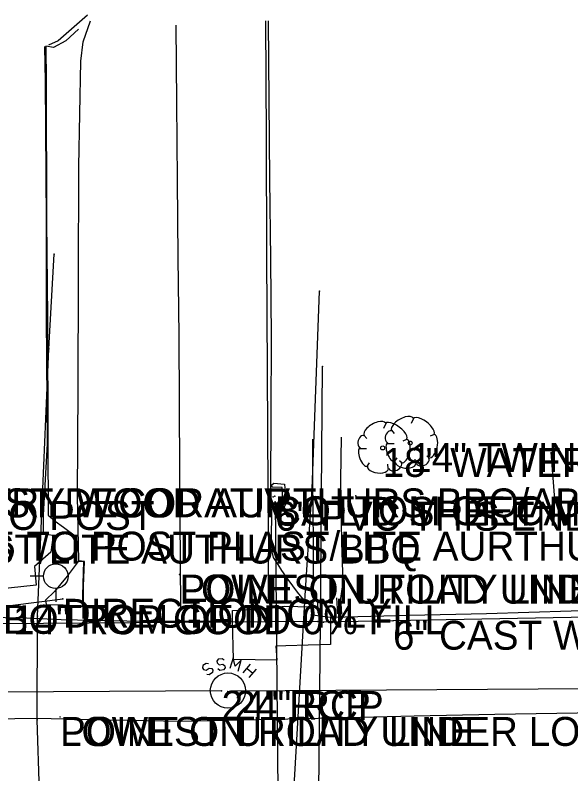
# Model space of a CAD drawing. Extents: x 1304270 to 1306561, y 1876019 to 1876752.
# Drawn here: x 1305896.1 to 1305992.1, y 1876400.4 to 1876531.4 of the extents above; entities that cross this region are included whole.
import ezdxf

# ---------------------------------------------------------------- set-up
doc = ezdxf.new("R2010")
doc.units = 0
for name, color, linetype in [('S_BUILDING_ANNOT', 7, 'Continuous'), ('S_CROSS_DRAIN', 7, 'Continuous'), ('S_CROSS_DRAIN_ANNOT', 7, 'Continuous'), ('S_CURB', 7, 'Continuous'), ('S_DRG_PT_SYM', 7, 'Continuous'), ('S_EDGE_CONCRETE', 7, 'Continuous'), ('S_EDGE_PAVEMENT', 7, 'Continuous'), ('S_ELECTRIC_UTILITIES_ANNOT', 7, 'Continuous'), ('S_FENCE_ANNOT', 7, 'Continuous'), ('S_FIBER_OPTIC_CABLE', 7, 'Continuous'), ('S_GAS_UTILITIES', 7, 'Continuous'), ('S_MANHOLE_ANNOT', 7, 'Continuous'), ('S_MSC_PT_SYM', 7, 'Continuous'), ('S_PARKING', 7, 'Continuous'), ('S_PAVEMENT_CROWN', 7, 'Continuous'), ('S_SANITARY_SEWER', 7, 'Continuous'), ('S_SANITARY_SEWER_ANNOT', 7, 'Continuous'), ('S_SIDEWALK', 7, 'Continuous'), ('S_SIGN_ANNOT', 7, 'Continuous'), ('S_STORM_SEWER', 7, 'Continuous'), ('S_STORM_SEWER_ANNOT', 7, 'Continuous'), ('S_SURVEY_TEXT_ANNOT', 7, 'Continuous'), ('S_TREE', 7, 'Continuous'), ('S_TREE_ANNOT', 7, 'Continuous'), ('S_UTILITY_POLE', 7, 'Continuous'), ('S_UTL_PT_SYM', 7, 'Continuous'), ('S_WATER_UTILITIES', 7, 'Continuous'), ('S_WATER_UTILITIES_ANNOT', 7, 'Continuous')]:
    doc.layers.add(name, color=color, linetype=linetype)

msp = doc.modelspace()

# ---------------------------------------------------------------- linework, layer by layer
at = {"layer": 'S_CROSS_DRAIN'}
msp.add_line((1305895.71, 1876429.5), (1305904.32, 1876430.63), dxfattribs=at)
at = {"layer": 'S_CURB'}
for points in [[(1305908.59, 1876531.43), (1305903.51, 1876527.02), (1305901.83, 1876526.26)], [(1305940.28, 1876449.7), (1305940.32, 1876462.66), (1305940.37, 1876475.63), (1305940.25, 1876489.33), (1305940.12, 1876503.04), (1305940, 1876516.74), (1305939.88, 1876530.45)], [(1305940.41, 1876440.32), (1305940.45, 1876446.22)]]:
    msp.add_lwpolyline(points, dxfattribs=at)
at = {"layer": 'S_DRG_PT_SYM'}
for points in [[(1305939.98, 1876448.32), (1305939.98, 1876448.37), (1305939.98, 1876448.32), (1305939.93, 1876448.32), (1305939.98, 1876448.32), (1305939.98, 1876448.27), (1305939.98, 1876448.32), (1305940.03, 1876448.32)], [(1305904.32, 1876430.63), (1305904.32, 1876430.68), (1305904.32, 1876430.63), (1305904.27, 1876430.63), (1305904.32, 1876430.63), (1305904.32, 1876430.58), (1305904.32, 1876430.63), (1305904.37, 1876430.63)]]:
    msp.add_lwpolyline(points, dxfattribs=at)
at = {"layer": 'S_EDGE_CONCRETE'}
for points in [[(1305907.04, 1876529.01), (1305904.85, 1876527.01), (1305902.71, 1876525.83), (1305901.42, 1876526.07), (1305901.43, 1876519.97), (1305901.54, 1876495.9), (1305901.67, 1876479.35), (1305901.72, 1876457.32), (1305901.82, 1876445.05), (1305903.03, 1876444.04), (1305904.46, 1876443.02), (1305906.71, 1876441.34)], [(1305907.98, 1876437.05), (1305906.98, 1876437.06), (1305905.09, 1876434.52), (1305902.88, 1876431.9), (1305901.35, 1876430.4), (1305901.46, 1876429.63), (1305904.37, 1876429.56), (1305907.73, 1876429.31)], [(1305907.73, 1876429.31), (1305907.98, 1876437.05)], [(1305948.36, 1876430.46), (1305948.38, 1876428.14)], [(1305951.61, 1876430.81), (1305951.79, 1876428.01)]]:
    msp.add_lwpolyline(points, dxfattribs=at)
for points in [[(1305940.8, 1876450.61), (1305942.61, 1876450.43), (1305942.82, 1876448.35), (1305942.83, 1876446.97), (1305942.56, 1876446.44), (1305940.64, 1876446.31), (1305940.05, 1876446.68), (1305939.95, 1876447.02), (1305942.34, 1876447.04), (1305942.21, 1876449.87), (1305940.49, 1876449.9), (1305940.47, 1876450.32)], [(1305933.68, 1876428.63), (1305940.15, 1876429.02), (1305942.56, 1876429.36), (1305947.28, 1876429.25), (1305947.49, 1876427.88), (1305950.61, 1876427.48), (1305950.6, 1876422.74), (1305942.85, 1876422.5), (1305941.15, 1876422.43), (1305941.34, 1876420.01), (1305933.8, 1876420.14), (1305933.63, 1876426.92)]]:
    msp.add_lwpolyline(points, close=True, dxfattribs=at)
at = {"layer": 'S_EDGE_PAVEMENT'}
for points in [[(1305907.83, 1876427.25), (1305907.92, 1876432.8), (1305908.08, 1876437.07), (1305907.09, 1876437.19), (1305906.89, 1876448.38), (1305906.97, 1876467.11), (1305907.06, 1876485.85), (1305907.09, 1876505.27), (1305907.44, 1876523.51), (1305907.87, 1876526.84), (1305909.11, 1876530.43)], [(1305940.14, 1876429.1), (1305939.87, 1876434.23), (1305939.95, 1876440.19), (1305939.82, 1876447.23), (1305939.8, 1876449.61), (1305939.7, 1876469.82), (1305939.6, 1876490.04), (1305939.5, 1876510.26), (1305939.4, 1876530.48)], [(1305946.44, 1876429.9), (1305944.89, 1876431.78), (1305943.28, 1876433.95), (1305942.18, 1876435.54), (1305941.56, 1876436.58), (1305940.76, 1876437.76), (1305940.29, 1876439.71)], [(1305950.89, 1876427.47), (1305964.22, 1876427.79), (1305977.54, 1876428.11), (1305992.2, 1876428.56), (1306006.85, 1876429.02), (1306028.93, 1876429.57), (1306053.46, 1876429.57), (1306077.99, 1876429.56), (1306100.79, 1876429.97)], [(1305650.55, 1876423.21), (1305674.32, 1876423.35), (1305698.09, 1876423.48), (1305721.97, 1876423.8), (1305745.85, 1876424.12), (1305770.29, 1876424.67), (1305794.74, 1876425.23), (1305811.42, 1876425.85), (1305825.07, 1876426.72), (1305843.96, 1876426.78), (1305860.03, 1876426.98), (1305876.09, 1876427.18), (1305883.24, 1876427.59), (1305898.06, 1876427.36), (1305904.05, 1876427.05), (1305918.23, 1876426.76), (1305933.32, 1876426.78)]]:
    msp.add_lwpolyline(points, dxfattribs=at)
at = {"layer": 'S_FIBER_OPTIC_CABLE'}
for p, q in [((1305947.43, 1876449.62), (1305948.69, 1876483.76)), ((1305946.25, 1876432.14), (1305947.43, 1876449.62)), ((1305944.24, 1876396.69), (1305946.25, 1876432.14))]:
    msp.add_line(p, q, dxfattribs=at)
at = {"layer": 'S_GAS_UTILITIES'}
for p, q in [((1305901.93, 1876473.82), (1305902.81, 1876490.17)), ((1305900.89, 1876449.65), (1305901.93, 1876473.82)), ((1305899.97, 1876427.63), (1305900.89, 1876449.65)), ((1305899.88, 1876409.72), (1305899.97, 1876427.63)), ((1305900.53, 1876390.42), (1305899.88, 1876409.72))]:
    msp.add_line(p, q, dxfattribs=at)
at = {"layer": 'S_MSC_PT_SYM'}
for points in [[(1305940.67, 1876448.24), (1305940.67, 1876448.29), (1305940.67, 1876448.24), (1305940.62, 1876448.24), (1305940.67, 1876448.24), (1305940.67, 1876448.19), (1305940.67, 1876448.24), (1305940.72, 1876448.24)], [(1305924.49, 1876434.8), (1305924.49, 1876434.85), (1305924.49, 1876434.8), (1305924.44, 1876434.8), (1305924.49, 1876434.8), (1305924.49, 1876434.75), (1305924.49, 1876434.8), (1305924.54, 1876434.8)], [(1305903.85, 1876410.22), (1305903.85, 1876410.27), (1305903.85, 1876410.22), (1305903.8, 1876410.22), (1305903.85, 1876410.22), (1305903.85, 1876410.17), (1305903.85, 1876410.22), (1305903.9, 1876410.22)]]:
    msp.add_lwpolyline(points, dxfattribs=at)
at = {"layer": 'S_PARKING'}
msp.add_lwpolyline([(1305901.16, 1876526.05), (1305901.3, 1876519.98), (1305901.45, 1876495.85), (1305901.48, 1876479.31), (1305901.6, 1876457.42), (1305900.96, 1876445.11), (1305900.93, 1876443.49), (1305900.91, 1876441.84), (1305902.67, 1876441.64), (1305902.25, 1876438.69), (1305899.45, 1876436.19), (1305899.74, 1876432.97), (1305894.96, 1876432.47), (1305890.73, 1876431.98), (1305878.86, 1876431.91), (1305857.12, 1876431.13), (1305837.44, 1876430.83), (1305828.63, 1876431.93)], dxfattribs=at)
at = {"layer": 'S_PAVEMENT_CROWN'}
for points in [[(1305924.7, 1876428.99), (1305924.56, 1876452.55), (1305924.42, 1876476.1), (1305924.29, 1876489.51), (1305924.16, 1876502.91), (1305924.03, 1876516.32), (1305923.9, 1876529.72)], [(1305794.47, 1876408.96), (1305817.8, 1876409.07), (1305841.14, 1876409.19), (1305862.85, 1876409.5), (1305884.57, 1876409.8), (1305899.82, 1876410.02), (1305912.34, 1876409.75), (1305924.85, 1876409.48), (1305937.98, 1876409.78), (1305951.12, 1876410.08), (1305965.04, 1876410.39), (1305978.96, 1876410.71), (1306003.9, 1876411.1), (1306028.84, 1876411.5), (1306053.64, 1876411.74), (1306078.45, 1876411.98)]]:
    msp.add_lwpolyline(points, dxfattribs=at)
at = {"layer": 'S_SANITARY_SEWER'}
for p, q in [((1305928.55, 1876419.08), (1305928.47, 1876418.69)), ((1305928.47, 1876418.69), (1305928.66, 1876418.42)), ((1305929.09, 1876419.46), (1305928.55, 1876419.08)), ((1305929.51, 1876419.39), (1305929.09, 1876419.46)), ((1305929.09, 1876418.3), (1305929.63, 1876418.65)), ((1305929.63, 1876418.65), (1305930.1, 1876418.57)), ((1305930.1, 1876418.57), (1305930.25, 1876418.3)), ((1305935.52, 1876417.84), (1305936.76, 1876419.31)), ((1305936.18, 1876418.61), (1305937.15, 1876417.8)), ((1305928.66, 1876418.42), (1305929.09, 1876418.3)), ((1305929.63, 1876417.49), (1305929.24, 1876417.56)), ((1305930.17, 1876417.87), (1305929.63, 1876417.49)), ((1305930.25, 1876418.3), (1305930.17, 1876417.87)), ((1305937.73, 1876418.49), (1305936.49, 1876417.02)), ((1306231.1, 1876416.56), (1305933.99, 1876414.7)), ((1305931.77, 1876414.75), (1305628.57, 1876412.86))]:
    msp.add_line(p, q, dxfattribs=at)
for points in [[(1305932.19, 1876420.01), (1305931.84, 1876420.28), (1305931.18, 1876420.2), (1305930.95, 1876419.85), (1305930.99, 1876419.54), (1305931.34, 1876419.23), (1305931.96, 1876419.35), (1305932.34, 1876419.04), (1305932.38, 1876418.73), (1305932.11, 1876418.34), (1305931.49, 1876418.26), (1305931.14, 1876418.53)], [(1305934.63, 1876418.15), (1305935.17, 1876420.01), (1305934.13, 1876419), (1305933.74, 1876420.43), (1305933.2, 1876418.57)]]:
    msp.add_lwpolyline(points, dxfattribs=at)
msp.add_circle((1305932.87, 1876414.77), 3.05, dxfattribs=at)
at = {"layer": 'S_SIDEWALK'}
for points in [[(1305947.47, 1876458.19), (1305947.49, 1876451.36), (1305947.59, 1876440.3), (1305947.59, 1876433.46), (1305947.58, 1876431.19), (1305947.45, 1876428.17)], [(1305952.4, 1876458.53), (1305952.32, 1876451.22), (1305952.5, 1876440.33), (1305952.72, 1876433.49), (1305952.34, 1876430.66), (1305952.49, 1876427.99)], [(1305989.27, 1876445.05), (1305989.3, 1876448.54), (1305988.7, 1876455.95)]]:
    msp.add_lwpolyline(points, dxfattribs=at)
at = {"layer": 'S_STORM_SEWER'}
msp.add_line((1305941.01, 1876447.39), (1305941.73, 1876372.76), dxfattribs=at)
at = {"layer": 'S_TREE'}
for p, q in [((1305964.91, 1876461.77), (1305964.52, 1876460.92)), ((1305960.16, 1876460.92), (1305959.77, 1876460.07)), ((1305961.11, 1876459.76), (1305961.61, 1876459.18)), ((1305956.36, 1876458.91), (1305956.86, 1876458.33)), ((1305963.72, 1876458.13), (1305963.06, 1876457.86)), ((1305968.47, 1876458.98), (1305967.81, 1876458.71)), ((1305955.7, 1876456.58), (1305956.82, 1876456.58)), ((1305960.45, 1876457.43), (1305961.58, 1876457.43)), ((1305967.7, 1876454.87), (1305967.23, 1876455.3)), ((1305956.86, 1876453.41), (1305957.33, 1876454.1)), ((1305960.54, 1876453.14), (1305960.47, 1876453.91)), ((1305961.61, 1876454.25), (1305962.08, 1876454.95)), ((1305962.95, 1876454.03), (1305962.48, 1876454.45)), ((1305965.3, 1876453.98), (1305965.22, 1876454.76))]:
    msp.add_line(p, q, dxfattribs=at)
for centre in [(1305964.35, 1876457.53), (1305959.6, 1876456.68)]:
    msp.add_circle(centre, 0.341, dxfattribs=at)
for centre, major_axis, ratio, start_param, end_param in [((1305963.01, 1876460.73), (1.86, 1.08), 0.471018, 0, 3.141593), ((1305966.67, 1876460.4), (-1.81, 1.36), 0.405113, 3.141593, 6.283186), ((1305958.26, 1876459.88), (1.86, 1.08), 0.471018, 0, 3.141593), ((1305961.92, 1876459.56), (-1.81, 1.36), 0.405113, 3.141593, 6.283186), ((1305960.78, 1876458.61), (0.31, 1.03), 0.646762, 0, 3.141593), ((1305956.03, 1876457.77), (0.31, 1.03), 0.646762, 0, 3.141593), ((1305963.27, 1876456.15), (0.46, 2.04), 0.482994, 3.141593, 6.283185), ((1305968.02, 1876457), (0.46, 2.04), 0.482994, 3.141593, 6.283185), ((1305956.33, 1876455.12), (-0.61, 1.6), 0.420543, 6.283185, 9.424777), ((1305961.08, 1876455.96), (-0.61, 1.6), 0.420543, 6.283185, 9.424777), ((1305961.75, 1876453.63), (1.09, 0.46), 0.711534, 3.141592, 6.283185), ((1305963.55, 1876454.18), (-1.83, 0.19), 0.529943, 0, 3.141593), ((1305966.5, 1876454.48), (1.09, 0.46), 0.711534, 3.141592, 6.283185), ((1305958.79, 1876453.34), (-1.83, 0.19), 0.529943, 0, 3.141593)]:
    msp.add_ellipse(centre, major_axis=major_axis, ratio=ratio, start_param=start_param, end_param=end_param, dxfattribs=at)
at = {"layer": 'S_UTILITY_POLE'}
for p, q in [((1305903.11, 1876436.64), (1305903.11, 1876438.89)), ((1305901.01, 1876434.51), (1305898.69, 1876434.51)), ((1305903.18, 1876430.09), (1305903.18, 1876432.42))]:
    msp.add_line(p, q, dxfattribs=at)
msp.add_circle((1305903.11, 1876434.53), 2.13, dxfattribs=at)
at = {"layer": 'S_UTL_PT_SYM'}
for points in [[(1305902.81, 1876490.17), (1305902.81, 1876490.22), (1305902.81, 1876490.17), (1305902.76, 1876490.17), (1305902.81, 1876490.17), (1305902.81, 1876490.12), (1305902.81, 1876490.17), (1305902.86, 1876490.17)], [(1305948.69, 1876483.76), (1305948.69, 1876483.81), (1305948.69, 1876483.76), (1305948.64, 1876483.76), (1305948.69, 1876483.76), (1305948.69, 1876483.71), (1305948.69, 1876483.76), (1305948.74, 1876483.76)], [(1305901.93, 1876473.82), (1305901.93, 1876473.87), (1305901.93, 1876473.82), (1305901.88, 1876473.82), (1305901.93, 1876473.82), (1305901.93, 1876473.77), (1305901.93, 1876473.82), (1305901.98, 1876473.82)], [(1305949.2, 1876470.74), (1305949.2, 1876470.79), (1305949.2, 1876470.74), (1305949.15, 1876470.74), (1305949.2, 1876470.74), (1305949.2, 1876470.69), (1305949.2, 1876470.74), (1305949.25, 1876470.74)], [(1305900.89, 1876449.65), (1305900.89, 1876449.7), (1305900.89, 1876449.65), (1305900.84, 1876449.65), (1305900.89, 1876449.65), (1305900.89, 1876449.6), (1305900.89, 1876449.65), (1305900.94, 1876449.65)], [(1305947.43, 1876449.62), (1305947.43, 1876449.67), (1305947.43, 1876449.62), (1305947.38, 1876449.62), (1305947.43, 1876449.62), (1305947.43, 1876449.57), (1305947.43, 1876449.62), (1305947.48, 1876449.62)], [(1305940.98, 1876448.34), (1305940.98, 1876448.39), (1305940.98, 1876448.34), (1305940.93, 1876448.34), (1305940.98, 1876448.34), (1305940.98, 1876448.29), (1305940.98, 1876448.34), (1305941.03, 1876448.34)], [(1305941.01, 1876447.39), (1305941.01, 1876447.44), (1305941.01, 1876447.39), (1305940.96, 1876447.39), (1305941.01, 1876447.39), (1305941.01, 1876447.34), (1305941.01, 1876447.39), (1305941.06, 1876447.39)], [(1305954.97, 1876448.42), (1305954.97, 1876448.47), (1305954.97, 1876448.42), (1305954.92, 1876448.42), (1305954.97, 1876448.42), (1305954.97, 1876448.37), (1305954.97, 1876448.42), (1305955.02, 1876448.42)], [(1305924.49, 1876434.8), (1305924.49, 1876434.85), (1305924.49, 1876434.8), (1305924.44, 1876434.8), (1305924.49, 1876434.8), (1305924.49, 1876434.75), (1305924.49, 1876434.8), (1305924.54, 1876434.8)], [(1305946.25, 1876432.14), (1305946.25, 1876432.19), (1305946.25, 1876432.14), (1305946.2, 1876432.14), (1305946.25, 1876432.14), (1305946.25, 1876432.09), (1305946.25, 1876432.14), (1305946.3, 1876432.14)], [(1305899.97, 1876427.63), (1305899.97, 1876427.68), (1305899.97, 1876427.63), (1305899.92, 1876427.63), (1305899.97, 1876427.63), (1305899.97, 1876427.58), (1305899.97, 1876427.63), (1305900.02, 1876427.63)], [(1305948.37, 1876426.7), (1305948.37, 1876426.75), (1305948.37, 1876426.7), (1305948.32, 1876426.7), (1305948.37, 1876426.7), (1305948.37, 1876426.65), (1305948.37, 1876426.7), (1305948.42, 1876426.7)], [(1305948.87, 1876426.5), (1305948.87, 1876426.55), (1305948.87, 1876426.5), (1305948.82, 1876426.5), (1305948.87, 1876426.5), (1305948.87, 1876426.45), (1305948.87, 1876426.5), (1305948.92, 1876426.5)], [(1305949.38, 1876426.6), (1305949.38, 1876426.65), (1305949.38, 1876426.6), (1305949.33, 1876426.6), (1305949.38, 1876426.6), (1305949.38, 1876426.55), (1305949.38, 1876426.6), (1305949.43, 1876426.6)], [(1305961.38, 1876426.84), (1305961.38, 1876426.89), (1305961.38, 1876426.84), (1305961.33, 1876426.84), (1305961.38, 1876426.84), (1305961.38, 1876426.79), (1305961.38, 1876426.84), (1305961.43, 1876426.84)], [(1305931.77, 1876414.75), (1305931.77, 1876414.8), (1305931.77, 1876414.75), (1305931.72, 1876414.75), (1305931.77, 1876414.75), (1305931.77, 1876414.7), (1305931.77, 1876414.75), (1305931.82, 1876414.75)], [(1305932.85, 1876414.63), (1305932.85, 1876414.68), (1305932.85, 1876414.63), (1305932.8, 1876414.63), (1305932.85, 1876414.63), (1305932.85, 1876414.58), (1305932.85, 1876414.63), (1305932.9, 1876414.63)], [(1305933.99, 1876414.7), (1305933.99, 1876414.75), (1305933.99, 1876414.7), (1305933.94, 1876414.7), (1305933.99, 1876414.7), (1305933.99, 1876414.65), (1305933.99, 1876414.7), (1305934.04, 1876414.7)], [(1305899.88, 1876409.72), (1305899.88, 1876409.77), (1305899.88, 1876409.72), (1305899.83, 1876409.72), (1305899.88, 1876409.72), (1305899.88, 1876409.67), (1305899.88, 1876409.72), (1305899.93, 1876409.72)], [(1305903.85, 1876410.22), (1305903.85, 1876410.27), (1305903.85, 1876410.22), (1305903.8, 1876410.22), (1305903.85, 1876410.22), (1305903.85, 1876410.17), (1305903.85, 1876410.22), (1305903.9, 1876410.22)]]:
    msp.add_lwpolyline(points, dxfattribs=at)
at = {"layer": 'S_WATER_UTILITIES'}
for p, q in [((1305948.87, 1876426.5), (1305949.2, 1876470.74)), ((1305948.37, 1876426.7), (1305874.58, 1876426.18)), ((1305948.48, 1876388.8), (1305948.87, 1876426.5)), ((1305961.38, 1876426.84), (1305949.38, 1876426.6)), ((1306004.61, 1876427.63), (1305961.38, 1876426.84))]:
    msp.add_line(p, q, dxfattribs=at)

# ---------------------------------------------------------------- texts
at = {"layer": 'S_BUILDING_ANNOT'}
msp.add_text('1 STRY WOOD AURTHURS BBQ/ABANDO', height=5, dxfattribs=at).set_placement((1305881.31, 1876444.69))
at = {"layer": 'S_CROSS_DRAIN_ANNOT'}
for s, p in [('DIRECTION ONLY', (1305904.32, 1876425.63)), ('14" RCP GOOD 0% FILL', (1305895.71, 1876424.5))]:
    msp.add_text(s, height=5, dxfattribs=at).set_placement(p)
at = {"layer": 'S_ELECTRIC_UTILITIES_ANNOT'}
for p in [(1305924.49, 1876429.8), (1305903.85, 1876405.22)]:
    msp.add_text('POINT ON ROAD UNDER LOW L', height=5, dxfattribs=at).set_placement(p)
at = {"layer": 'S_FENCE_ANNOT'}
msp.add_text("6' CHAINLINK/MTL POST DECORATIV", height=5, dxfattribs=at).set_placement((1305824.93, 1876444.69))
at = {"layer": 'S_MANHOLE_ANNOT'}
for s, p in [('BOTTOM OF CA', (1305940.98, 1876443.34)), ('BOTTOM OF DI', (1305893.95, 1876424.58))]:
    msp.add_text(s, height=5, dxfattribs=at).set_placement(p)
at = {"layer": 'S_SANITARY_SEWER_ANNOT'}
for p in [(1305931.77, 1876409.75), (1305933.99, 1876409.7)]:
    msp.add_text('24" RCP', height=5, dxfattribs=at).set_placement(p)
at = {"layer": 'S_SIGN_ANNOT'}
for s, p in [("1' TO POST", (1305883.97, 1876442.52)), ('7.5 TO POST PLAST/LITE AURTHURS BBQ', (1305886.87, 1876437.23)), ("6' TO POST MTL/PLAST/LITE AUTHURS BBQ", (1305825.57, 1876436.72))]:
    msp.add_text(s, height=5, dxfattribs=at).set_placement(p)
at = {"layer": 'S_STORM_SEWER_ANNOT'}
msp.add_text('6" PVC THIS END OPEN', height=5, dxfattribs=at).set_placement((1305941.01, 1876442.39))
at = {"layer": 'S_SURVEY_TEXT_ANNOT'}
for s, p in [('CA LID SHEET MTL/REMOVBLE', (1305940.67, 1876443.24)), ('LOWEST UTILITY LINE', (1305924.49, 1876429.8)), ('LOWEST UTILITY LINE', (1305903.85, 1876405.22))]:
    msp.add_text(s, height=5, dxfattribs=at).set_placement(p)
at = {"layer": 'S_TREE_ANNOT'}
for s, p in [('18" WATER OAK', (1305959.6, 1876451.68)), ('14" TWIN OAK', (1305964.35, 1876452.53))]:
    msp.add_text(s, height=5, dxfattribs=at).set_placement(p)
at = {"layer": 'S_WATER_UTILITIES_ANNOT'}
msp.add_text('6" CAST WA', height=5, dxfattribs=at).set_placement((1305961.38, 1876421.84))

doc.saveas('drawing.dxf')
